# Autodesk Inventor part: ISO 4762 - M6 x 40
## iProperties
Comments: To add or edit properties for Autodesk Inventor files, use iProperties.
Created: 2004-08
Part Number: ISO 4762 - M6 x 40
Vendor: Autodesk Inc.
Document SubType Name: Modeling
Designer: John Blackburn
Material: Default
Description: Hexagon Socket Head Cap Screw
Standard: ISO 4762
Size Designation: M6 x 40
Alert: To add or edit properties for Autodesk Inventor files, use iProperties.
Control State: 0
Master: False
Checked Out: False
Shininess: 64.0
Length Units: 11269
Angle Units: 11279
Time Units: 11290
Mass Units: 11283
Length Display Precision: 3
Angle Display Precision: 2
Compacted: True
EGR: 1
Density: 0.0
Volumn: 0.0
Area: 0.0
PropertySet Name: Model Information
Author: John Blackburn
Revision Number: 8
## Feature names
1. Body [Revolution]
2. Slot [Extrusion]
3. Fillet1
4. Chamfer1
